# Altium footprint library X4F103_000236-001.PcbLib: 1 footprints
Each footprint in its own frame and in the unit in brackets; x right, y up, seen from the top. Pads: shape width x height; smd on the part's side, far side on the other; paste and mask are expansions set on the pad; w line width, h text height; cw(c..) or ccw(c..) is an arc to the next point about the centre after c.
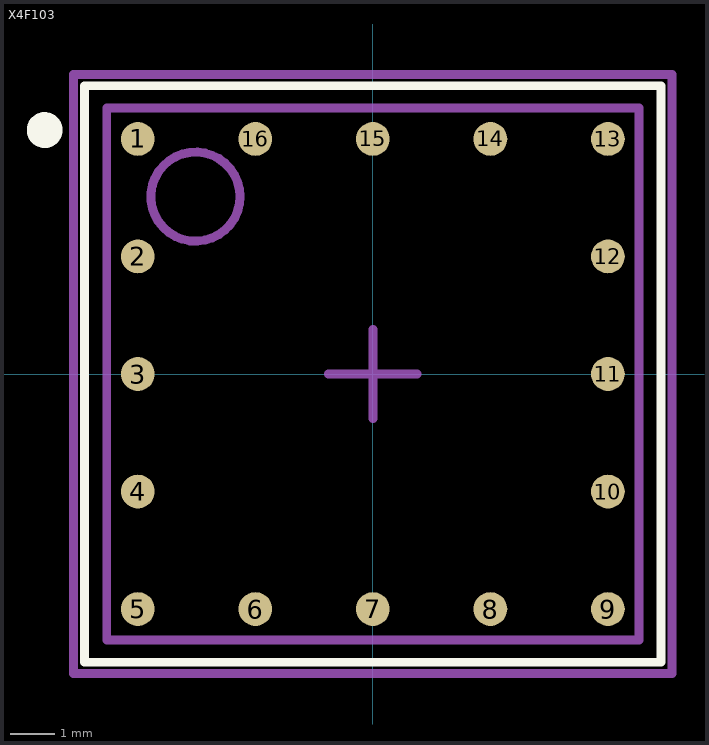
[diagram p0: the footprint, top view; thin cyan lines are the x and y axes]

## X4F103 [mil] "X4F103 Footprint"
pads (16):
  round 30 smd mask-1.57: 1(-208.66,208.66) 2(-208.66,104.33) 3(-208.66,0) 4(-208.66,-104.33) 5(-208.66,-208.66) 6(-104.33,-208.66) 7(0,-208.66) 8(104.33,-208.66) 9(208.66,-208.66) 10(208.66,-104.33) 11(208.66,0) 12(208.66,104.33) 13(208.66,208.66) 14(104.33,208.66) 15(0,208.66) 16(-104.33,208.66)
Top Overlay:
  circle w16.14: c-291.34,216.54 r7.87
  lines w7.87: -255.91,-255.91 255.91,-255.91 255.91,255.91 -255.91,255.91 -255.91,-255.91
Top Courtyard:
  lines w7.87: -265.75,-265.75 265.75,-265.75 265.75,265.75 -265.75,265.75 -265.75,-265.75
Top Assembly:
  circle w7.87: c-157.48,157.48 r39.57
  lines w7.87: -236.22,-236.22 -236.22,236.22 236.22,236.22 236.22,-236.22 -236.22,-236.22
Top Component Center:
  lines w7.87: -39.37,0 39.37,0 ; 0,-39.37 0,39.37
3D body "X4F103.step": height 92.52, standoff 0.69, extent -236.22,-236.22 236.22,236.22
